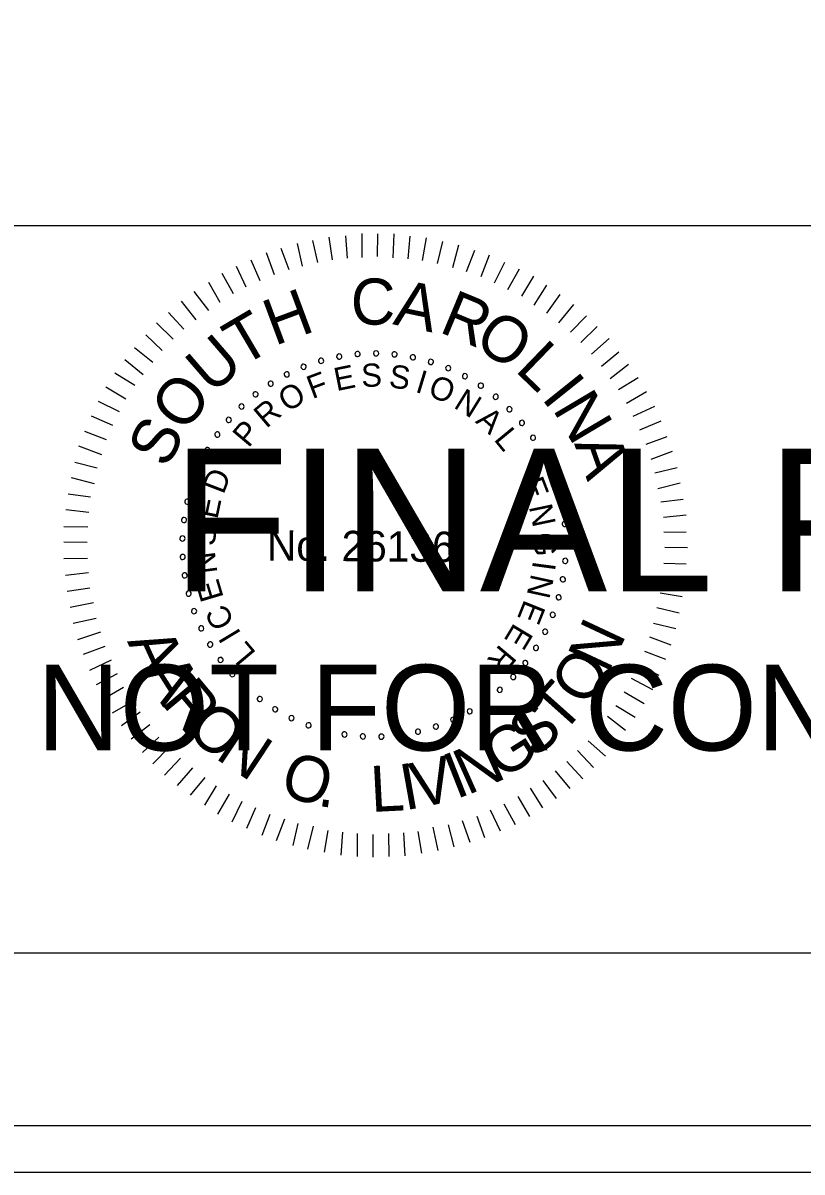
# Model space of a CAD drawing. Extents: x 967 to 1326, y 964 to 3144.
# Drawn here: x 1170.56 to 1189.3, y 963.72 to 991.36 of the extents above; entities that cross this region are included whole.
import ezdxf

# ---------------------------------------------------------------- set-up
doc = ezdxf.new("R2010")
doc.units = 0
for name, color, linetype in [('RD_XS_EwShp', 7, 'Continuous'), ('RD_XS_ExPaveRet', 7, 'Continuous'), ('RD_XS_TX_Elev_EX', 7, 'Continuous'), ('RD_XS_TX_Elev_PR', 7, 'Continuous'), ('RD_XS_TX_Station', 7, 'Continuous')]:
    doc.layers.add(name, color=color, linetype=linetype)

msp = doc.modelspace()

# ---------------------------------------------------------------- linework, layer by layer
at = {"layer": 'RD_XS_ExPaveRet'}
for points in [[(967.409, 963.72), (1326.285, 963.72), (1326.285, 1183.72), (967.409, 1183.72)], [(988.525, 964.84), (1326.285, 964.84), (1326.285, 1182.6), (988.525, 1182.6)]]:
    msp.add_lwpolyline(points, close=True, dxfattribs=at)
at = {"layer": 'RD_XS_TX_Elev_EX'}
for p, q in [((996.114, 986.486), (1323.886, 986.486)), ((1323.886, 968.983), (996.114, 968.983))]:
    msp.add_line(p, q, dxfattribs=at)
at = {"layer": 'RD_XS_TX_Elev_PR'}
for p, q in [((1178.01, 985.663), (1177.93, 986.209)), ((1178.364, 985.699), (1178.33, 986.244)), ((1178.717, 985.719), (1178.722, 986.295)), ((1179.093, 985.739), (1179.098, 986.292)), ((1179.469, 985.713), (1179.489, 986.288)), ((1179.829, 985.687), (1179.872, 986.231)), ((1180.174, 985.646), (1180.271, 986.19)), ((1176.964, 985.419), (1176.769, 985.935)), ((1177.287, 985.508), (1177.169, 986.054)), ((1177.657, 985.597), (1177.53, 986.128)), ((1180.535, 985.573), (1180.662, 986.102)), ((1180.902, 985.478), (1181.045, 986.022)), ((1176.264, 985.156), (1176.053, 985.657)), ((1176.61, 985.306), (1176.423, 985.83)), ((1181.231, 985.384), (1181.428, 985.896)), ((1181.584, 985.265), (1181.78, 985.786)), ((1175.933, 985.005), (1175.699, 985.506)), ((1181.905, 985.109), (1182.154, 985.606)), ((1182.226, 984.953), (1182.506, 985.45)), ((1175.308, 984.634), (1175.036, 985.12)), ((1175.624, 984.846), (1175.352, 985.332)), ((1182.562, 984.789), (1182.85, 985.27)), ((1175.03, 984.445), (1174.681, 984.9)), ((1182.86, 984.572), (1183.163, 985.053)), ((1183.158, 984.378), (1183.484, 984.828)), ((1174.729, 984.217), (1174.372, 984.665)), ((1183.447, 984.145), (1183.811, 984.587)), ((1174.435, 983.997), (1174.062, 984.399)), ((1183.729, 983.92), (1184.116, 984.316)), ((1174.172, 983.753), (1173.776, 984.148)), ((1183.98, 983.672), (1184.368, 984.061)), ((1173.909, 983.479), (1173.52, 983.858)), ((1184.232, 983.394), (1184.657, 983.767)), ((1173.684, 983.197), (1173.242, 983.546)), ((1184.475, 983.108), (1184.892, 983.45)), ((1173.451, 982.9), (1173.009, 983.256)), ((1184.687, 982.807), (1185.128, 983.156)), ((1173.257, 982.64), (1172.776, 982.936)), ((1173.039, 982.312), (1172.559, 982.6)), ((1184.885, 982.544), (1185.355, 982.832)), ((1185.081, 982.213), (1185.56, 982.493)), ((1172.883, 982.006), (1172.379, 982.256)), ((1185.24, 981.904), (1185.756, 982.145)), ((1172.727, 981.677), (1172.215, 981.904)), ((1185.399, 981.573), (1185.907, 981.791)), ((1172.571, 981.333), (1172.051, 981.53)), ((1185.549, 981.226), (1186.057, 981.414)), ((1172.461, 980.974), (1171.91, 981.178)), ((1185.669, 980.865), (1186.185, 981.06)), ((1172.351, 980.652), (1171.807, 980.787)), ((1185.759, 980.541), (1186.297, 980.667)), ((1172.286, 980.276), (1171.727, 980.419)), ((1185.832, 980.165), (1186.371, 980.298)), ((1172.191, 979.955), (1171.647, 980.029)), ((1185.906, 979.842), (1186.436, 979.906)), ((1172.15, 979.587), (1171.598, 979.653)), ((1185.964, 979.473), (1186.51, 979.53)), ((1172.124, 979.234), (1171.548, 979.239)), ((1185.977, 979.12), (1186.514, 979.115)), ((1172.105, 978.866), (1171.545, 978.871)), ((1185.997, 978.751), (1186.542, 978.747)), ((1172.118, 978.482), (1171.542, 978.471)), ((1185.971, 978.368), (1186.508, 978.348)), ((1172.138, 978.136), (1171.585, 978.072)), ((1185.952, 978.022), (1186.497, 977.949)), ((1172.173, 977.768), (1171.627, 977.688)), ((1185.888, 977.655), (1186.417, 977.566)), ((1172.262, 977.414), (1171.701, 977.296)), ((1185.808, 977.302), (1186.345, 977.175)), ((1172.321, 977.037), (1171.774, 976.911)), ((1185.729, 976.926), (1186.265, 976.792)), ((1172.425, 976.707), (1171.871, 976.519)), ((1185.634, 976.597), (1186.146, 976.401)), ((1172.53, 976.36), (1172.007, 976.173)), ((1185.508, 976.253), (1186.013, 976.057)), ((1172.681, 976.029), (1172.165, 975.788)), ((1172.831, 975.705), (1172.323, 975.441)), ((1185.352, 975.924), (1185.857, 975.675)), ((1185.188, 975.603), (1185.7, 975.33)), ((1172.982, 975.374), (1172.497, 975.094)), ((1185.024, 975.274), (1185.498, 974.987)), ((1173.194, 975.042), (1172.709, 974.762)), ((1184.822, 974.946), (1185.288, 974.658)), ((1173.384, 974.78), (1172.936, 974.453)), ((1184.62, 974.687), (1185.055, 974.353)), ((1173.612, 974.478), (1173.164, 974.129)), ((1184.403, 974.389), (1184.814, 974.033)), ((1173.832, 974.177), (1173.437, 973.812)), ((1184.155, 974.092), (1184.574, 973.72)), ((1174.091, 973.945), (1173.689, 973.541)), ((1183.899, 973.864), (1184.28, 973.454)), ((1174.35, 973.674), (1173.97, 973.263)), ((1183.644, 973.597), (1184.024, 973.18)), ((1174.64, 973.442), (1174.275, 973.022)), ((1174.937, 973.209), (1174.58, 972.782)), ((1183.358, 973.37), (1183.715, 972.944)), ((1175.212, 973.014), (1174.932, 972.549)), ((1182.764, 972.952), (1183.059, 972.482)), ((1183.065, 973.141), (1183.384, 972.709)), ((1175.525, 972.812), (1175.245, 972.331)), ((1182.463, 972.755), (1182.743, 972.269)), ((1175.83, 972.633), (1175.588, 972.136)), ((1176.159, 972.477), (1175.94, 971.98)), ((1181.8, 972.431), (1182.041, 971.93)), ((1182.124, 972.581), (1182.396, 972.08)), ((1176.503, 972.321), (1176.307, 971.816)), ((1176.855, 972.211), (1176.651, 971.69)), ((1177.177, 972.1), (1177.05, 971.572)), ((1181.122, 972.175), (1181.31, 971.652)), ((1181.476, 972.28), (1181.664, 971.771)), ((1177.545, 972.036), (1177.409, 971.484)), ((1177.897, 971.933), (1177.808, 971.412)), ((1178.25, 971.892), (1178.207, 971.34)), ((1178.603, 971.866), (1178.598, 971.313)), ((1178.978, 971.84), (1178.974, 971.295)), ((1179.355, 971.86), (1179.365, 971.307)), ((1179.715, 971.88), (1179.749, 971.327)), ((1180.061, 971.915), (1180.149, 971.393)), ((1180.423, 972.012), (1180.541, 971.458)), ((1180.791, 972.07), (1180.926, 971.54))]:
    msp.add_line(p, q, dxfattribs=at)
for centre, start, end in [((1178.609, 983.397), 5.0653, 185.0653), ((1179.055, 983.414), 359.5268, 179.5268), ((1179.5, 983.388), 353.9884, 173.9884), ((1177.312, 983.091), 21.6807, 201.6807), ((1177.734, 983.235), 16.1422, 196.1422), ((1177.734, 983.235), 196.1422, 16.1422), ((1178.168, 983.337), 10.6038, 190.6038), ((1178.168, 983.337), 190.6038, 10.6038), ((1178.609, 983.397), 185.0653, 5.0653), ((1179.055, 983.414), 179.5268, 359.5268), ((1179.5, 983.388), 173.9884, 353.9884), ((1179.94, 983.319), 168.4499, 348.4499), ((1179.94, 983.319), 348.4499, 168.4499), ((1180.372, 983.208), 162.9114, 342.9114), ((1180.372, 983.208), 342.9114, 162.9114), ((1176.906, 982.908), 27.2191, 207.2191), ((1176.906, 982.908), 207.2191, 27.2191), ((1177.312, 983.091), 201.6807, 21.6807), ((1180.79, 983.056), 157.373, 337.373), ((1180.79, 983.056), 337.373, 157.373), ((1181.193, 982.864), 151.8345, 331.8345), ((1181.193, 982.864), 331.8345, 151.8345), ((1176.52, 982.686), 32.7576, 212.7576), ((1176.52, 982.686), 212.7576, 32.7576), ((1181.574, 982.634), 146.2961, 326.2961), ((1181.574, 982.634), 326.2961, 146.2961), ((1176.156, 982.428), 38.2961, 218.2961), ((1176.156, 982.428), 218.2961, 38.2961), ((1181.932, 982.368), 140.7576, 320.7576), ((1181.932, 982.368), 320.7576, 140.7576), ((1175.82, 982.135), 43.8345, 223.8345), ((1175.82, 982.135), 223.8345, 43.8345), ((1182.263, 982.069), 135.2191, 315.2191), ((1182.263, 982.069), 315.2191, 135.2191), ((1175.513, 981.812), 49.373, 229.373), ((1175.513, 981.812), 229.373, 49.373), ((1182.563, 981.74), 129.6807, 309.6807), ((1182.563, 981.74), 309.6807, 129.6807), ((1175.239, 981.461), 54.9114, 234.9114), ((1175.239, 981.461), 234.9114, 54.9114), ((1182.83, 981.383), 124.1422, 304.1422), ((1182.83, 981.383), 304.1422, 124.1422), ((1175, 981.085), 60.4499, 240.4499), ((1175, 981.085), 240.4499, 60.4499), ((1183.061, 981.002), 118.6038, 298.6038), ((1183.061, 981.002), 298.6038, 118.6038), ((1174.798, 980.687), 65.9884, 245.9884), ((1174.798, 980.687), 245.9884, 65.9884), ((1183.255, 980.601), 293.0653, 113.0653), ((1183.255, 980.601), 113.0653, 293.0653), ((1174.636, 980.272), 71.5268, 251.5268), ((1174.636, 980.272), 251.5268, 71.5268), ((1183.408, 980.182), 107.5268, 287.5268), ((1183.408, 980.182), 287.5268, 107.5268), ((1174.514, 979.843), 77.0653, 257.0653), ((1174.514, 979.843), 257.0653, 77.0653), ((1183.521, 979.751), 101.9884, 281.9884), ((1183.521, 979.751), 281.9884, 101.9884), ((1174.435, 979.405), 82.6038, 262.6038), ((1174.435, 979.405), 262.6038, 82.6038), ((1183.592, 979.311), 96.4499, 276.4499), ((1183.592, 979.311), 276.4499, 96.4499), ((1174.398, 978.961), 88.1422, 268.1422), ((1174.398, 978.961), 268.1422, 88.1422), ((1183.619, 978.866), 90.9114, 270.9114), ((1183.619, 978.866), 270.9114, 90.9114), ((1174.404, 978.515), 93.6807, 273.6807), ((1174.404, 978.515), 273.6807, 93.6807), ((1183.604, 978.421), 85.373, 265.373), ((1183.604, 978.421), 265.373, 85.373), ((1174.453, 978.072), 99.2191, 279.2191), ((1174.453, 978.072), 279.2191, 99.2191), ((1183.546, 977.979), 79.8345, 259.8345), ((1183.546, 977.979), 259.8345, 79.8345), ((1174.545, 977.636), 104.7576, 284.7576), ((1174.545, 977.636), 284.7576, 104.7576), ((1183.445, 977.545), 74.2961, 254.2961), ((1183.445, 977.545), 254.2961, 74.2961), ((1174.678, 977.211), 110.2961, 290.2961), ((1174.678, 977.211), 290.2961, 110.2961), ((1183.303, 977.122), 68.7576, 248.7576), ((1183.303, 977.122), 248.7576, 68.7576), ((1174.852, 976.8), 115.8345, 295.8345), ((1174.852, 976.8), 295.8345, 115.8345), ((1183.121, 976.716), 63.2191, 243.2191), ((1183.121, 976.716), 243.2191, 63.2191), ((1175.065, 976.409), 121.373, 301.373), ((1175.065, 976.409), 301.373, 121.373), ((1182.9, 976.328), 57.6807, 237.6807), ((1182.9, 976.328), 237.6807, 57.6807), ((1175.314, 976.039), 126.9114, 306.9114), ((1175.314, 976.039), 306.9114, 126.9114), ((1182.643, 975.964), 52.1422, 232.1422), ((1182.643, 975.964), 232.1422, 52.1422), ((1175.598, 975.696), 132.4499, 312.4499), ((1175.598, 975.696), 312.4499, 132.4499), ((1182.353, 975.627), 46.6038, 226.6038), ((1175.914, 975.381), 137.9884, 317.9884), ((1175.914, 975.381), 317.9884, 137.9884), ((1182.353, 975.627), 226.6038, 46.6038), ((1176.258, 975.099), 143.5268, 323.5268), ((1176.258, 975.099), 323.5268, 143.5268), ((1182.03, 975.319), 41.0653, 221.0653), ((1182.03, 975.319), 221.0653, 41.0653), ((1176.629, 974.851), 149.0653, 329.0653), ((1176.629, 974.851), 329.0653, 149.0653), ((1181.305, 974.803), 29.9884, 209.9884), ((1181.68, 975.043), 35.5268, 215.5268), ((1181.68, 975.043), 215.5268, 35.5268), ((1177.021, 974.639), 154.6038, 334.6038), ((1177.021, 974.639), 334.6038, 154.6038), ((1180.908, 974.6), 24.4499, 204.4499), ((1180.908, 974.6), 204.4499, 24.4499), ((1181.305, 974.803), 209.9884, 29.9884), ((1177.432, 974.467), 160.1422, 340.1422), ((1177.432, 974.467), 340.1422, 160.1422), ((1177.858, 974.335), 165.6807, 345.6807), ((1177.858, 974.335), 345.6807, 165.6807), ((1178.294, 974.245), 351.2191, 171.2191), ((1180.065, 974.313), 13.373, 193.373), ((1180.065, 974.313), 193.373, 13.373), ((1180.494, 974.436), 18.9114, 198.9114), ((1180.494, 974.436), 198.9114, 18.9114), ((1178.294, 974.245), 171.2191, 351.2191), ((1178.737, 974.198), 356.7576, 176.7576), ((1178.737, 974.198), 176.7576, 356.7576), ((1179.183, 974.193), 2.2961, 182.2961), ((1179.183, 974.193), 182.2961, 2.2961), ((1179.627, 974.232), 7.8345, 187.8345), ((1179.627, 974.232), 187.8345, 7.8345)]:
    msp.add_arc(centre, 0.0627, start, end, dxfattribs=at)
at = {"layer": 'RD_XS_TX_Station'}
msp.add_lwpolyline([(967.409, 963.72), (1326.285, 963.72), (1326.285, 1183.72), (967.409, 1183.72)], close=True, dxfattribs=at)

# ---------------------------------------------------------------- texts
at = {"layer": 'RD_XS_EwShp'}
for s, height, p in [('FINAL PLANS', 3.4375, (1174.145, 977.685)), ('NOT FOR CONSTRUCTION', 2.0625, (1170.901, 973.86))]:
    msp.add_text(s, height=height, dxfattribs=at).set_placement(p)
at = {"layer": 'RD_XS_TX_Elev_PR'}
for s, height, rotation, p in [('C', 1.11, 359.5482, (1178.442, 984.108)), ('A', 1.11, 348.1981, (1179.439, 984.115)), ('H', 1.11, 20.3637, (1176.614, 983.587)), ('R', 1.11, 337.4344, (1180.541, 983.937)), ('T', 1.11, 30.4992, (1175.828, 983.072)), ('O', 1.108, 326.5869, (1181.366, 983.609)), ('U', 1.11, 40.8022, (1175.102, 982.403)), ('L', 1.11, 315.9488, (1182.373, 983.003)), ('S', 0.557, 2.208, (1178.709, 982.601)), ('F', 0.557, 20.6127, (1177.52, 982.309)), ('E', 0.557, 11.4103, (1178.103, 982.503)), ('S', 0.557, 352.6608, (1179.346, 982.599)), ('I', 0.557, 343.1136, (1179.975, 982.491)), ('I', 1.11, 308.6613, (1183.011, 982.338)), ('O', 1.11, 52.0267, (1174.435, 981.474)), ('O', 0.557, 30.8477, (1176.917, 981.987)), ('O', 0.557, 338.4392, (1180.274, 982.401)), ('N', 0.557, 328.2042, (1180.896, 982.12)), ('N', 1.11, 300.7037, (1183.285, 982.075)), ('R', 0.557, 40.3949, (1176.415, 981.594)), ('A', 0.557, 318.657, (1181.424, 981.762)), ('S', 1.108, 63.2511, (1174.029, 980.619)), ('P', 0.557, 49.9421, (1175.985, 981.124)), ('L', 0.557, 309.4546, (1181.869, 981.339)), ('A', 1.11, 289.4792, (1183.814, 981.243)), ('D', 0.557, 69.0364, (1175.386, 980.003)), ('E', 0.557, 291.049, (1182.53, 980.307)), ('E', 0.557, 78.2388, (1175.238, 979.407)), ('N', 0.557, 281.8466, (1182.728, 979.726)), ('S', 0.557, 87.786, (1175.187, 978.772)), ('No. 26136', 0.7311, 359.5268, (1176.429, 978.43)), ('G', 0.557, 272.2995, (1182.833, 979.097)), ('N', 0.557, 97.3332, (1175.242, 978.137)), ('I', 0.557, 262.4084, (1182.83, 978.437)), ('E', 0.557, 106.5355, (1175.394, 977.541)), ('N', 0.557, 257.7339, (1182.789, 978.127)), ('E', 0.557, 248.1867, (1182.628, 977.511)), ('C', 0.557, 116.4266, (1175.661, 976.938)), ('E', 0.557, 238.9844, (1182.378, 976.949)), ('N', 1.105, 64.8922, (1184.632, 975.684)), ('A', 1.105, 294.7297, (1173.062, 976.486)), ('I', 0.557, 121.1011, (1175.823, 976.67)), ('L', 0.557, 129.9595, (1176.187, 976.204)), ('R', 0.557, 229.782, (1182.041, 976.435)), ('O', 1.105, 56.2059, (1184.102, 974.874)), ('A', 1.105, 302.2892, (1173.414, 975.72)), ('R', 1.105, 309.8487, (1173.865, 975.007)), ('T', 1.105, 48.2685, (1183.515, 974.211)), ('O', 1.105, 317.7861, (1174.434, 974.33)), ('S', 1.105, 40.3311, (1182.842, 973.636)), ('N', 1.105, 326.4725, (1175.158, 973.686)), ('G', 1.105, 32.0198, (1182.059, 973.14)), ('N', 1.105, 24.0824, (1181.252, 972.776)), ('O', 1.105, 342.3472, (1176.697, 972.82)), ('V', 1.105, 12.7741, (1180.033, 972.457)), ('I', 1.105, 21.4605, (1180.976, 972.681)), ('L', 1.105, 2.9677, (1178.943, 972.379)), ('I', 1.105, 10.1523, (1179.743, 972.418)), ('.', 1.105, 351.0336, (1177.623, 972.536))]:
    msp.add_text(s, height=height, rotation=rotation, dxfattribs=at).set_placement(p)

doc.saveas('drawing.dxf')
